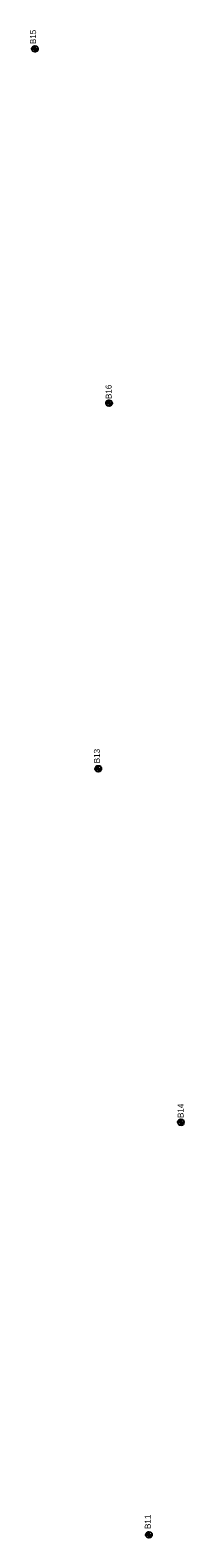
# Model space of a CAD drawing. Extents: x 345549 to 379569, y 127949 to 230467.
# Drawn here: x 361165 to 361421, y 134289 to 136793 of the extents above; entities that cross this region are included whole.
import ezdxf

# ---------------------------------------------------------------- set-up
doc = ezdxf.new("R2010")
doc.units = 0
for name, color, linetype in [('E_SOIL_BORE1 [KAPUR_CADDS_LEVELS]', 7, 'Continuous'), ('E_SOIL_BORE2 [KAPUR_CADDS_LEVELS]', 7, 'Continuous'), ('P_MARK', 7, 'Continuous')]:
    doc.layers.add(name, color=color, linetype=linetype)

msp = doc.modelspace()

# ---------------------------------------------------------------- linework, layer by layer
at = {"layer": 'P_MARK'}
for p, q in [((361173.1, 136766.5), (361173.1, 136756.5)), ((361168.1, 136761.5), (361178.1, 136761.5)), ((361291.4, 136173.3), (361301.4, 136173.3)), ((361296.4, 136178.3), (361296.4, 136168.3)), ((361273.5, 135566.2), (361283.5, 135566.2)), ((361278.5, 135571.2), (361278.5, 135561.2)), ((361410.9, 134979.1), (361420.9, 134979.1)), ((361415.9, 134984.1), (361415.9, 134974.1)), ((361357.8, 134294.1), (361367.8, 134294.1)), ((361362.8, 134299.1), (361362.8, 134289.1))]:
    msp.add_line(p, q, dxfattribs=at)
for centre in [(361173.1, 136761.5), (361296.4, 136173.3), (361278.5, 135566.2), (361415.9, 134979.1), (361362.8, 134294.1)]:
    msp.add_circle(centre, 5, dxfattribs=at)
for centre, radius, start, end in [((361173.1, 136761.5), 4.5, 89.9869, 179.9869), ((361173.1, 136761.5), 4, 89.9869, 179.9869), ((361173.1, 136761.5), 3.5, 89.9869, 179.9869), ((361173.1, 136761.5), 3, 89.9869, 179.9869), ((361173.1, 136761.5), 2.5, 89.9869, 179.9869), ((361173.1, 136761.5), 2, 89.9869, 179.9869), ((361173.1, 136761.5), 1.5, 89.9869, 179.9869), ((361173.1, 136761.5), 1, 89.9869, 179.9869), ((361173.1, 136761.5), 0.5, 89.9869, 179.9869), ((361173.1, 136761.5), 4.5, 269.9869, 359.9869), ((361173.1, 136761.5), 4, 269.9869, 359.9869), ((361173.1, 136761.5), 3.5, 269.9869, 359.9869), ((361173.1, 136761.5), 3, 269.9869, 359.9869), ((361173.1, 136761.5), 2.5, 269.9869, 359.9869), ((361173.1, 136761.5), 2, 269.9869, 359.9869), ((361173.1, 136761.5), 1.5, 269.9869, 359.9869), ((361173.1, 136761.5), 1, 269.9869, 359.9869), ((361173.1, 136761.5), 0.5, 269.9869, 359.9869), ((361296.4, 136173.3), 4.5, 89.9869, 179.9869), ((361296.4, 136173.3), 4, 89.9869, 179.9869), ((361296.4, 136173.3), 3.5, 89.9869, 179.9869), ((361296.4, 136173.3), 3, 89.9869, 179.9869), ((361296.4, 136173.3), 2.5, 89.9869, 179.9869), ((361296.4, 136173.3), 2, 89.9869, 179.9869), ((361296.4, 136173.3), 1.5, 89.9869, 179.9869), ((361296.4, 136173.3), 1, 89.9869, 179.9869), ((361296.4, 136173.3), 0.5, 89.9869, 179.9869), ((361296.4, 136173.3), 4.5, 269.9869, 359.9869), ((361296.4, 136173.3), 4, 269.9869, 359.9869), ((361296.4, 136173.3), 3.5, 269.9869, 359.9869), ((361296.4, 136173.3), 3, 269.9869, 359.9869), ((361296.4, 136173.3), 2.5, 269.9869, 359.9869), ((361296.4, 136173.3), 2, 269.9869, 359.9869), ((361296.4, 136173.3), 1.5, 269.9869, 359.9869), ((361296.4, 136173.3), 1, 269.9869, 359.9869), ((361296.4, 136173.3), 0.5, 269.9869, 359.9869), ((361278.5, 135566.2), 4.5, 89.9869, 179.9869), ((361278.5, 135566.2), 4, 89.9869, 179.9869), ((361278.5, 135566.2), 3.5, 89.9869, 179.9869), ((361278.5, 135566.2), 3, 89.9869, 179.9869), ((361278.5, 135566.2), 2.5, 89.9869, 179.9869), ((361278.5, 135566.2), 2, 89.9869, 179.9869), ((361278.5, 135566.2), 1.5, 89.9869, 179.9869), ((361278.5, 135566.2), 1, 89.9869, 179.9869), ((361278.5, 135566.2), 0.5, 89.9869, 179.9869), ((361278.5, 135566.2), 4.5, 269.9869, 359.9869), ((361278.5, 135566.2), 4, 269.9869, 359.9869), ((361278.5, 135566.2), 3.5, 269.9869, 359.9869), ((361278.5, 135566.2), 3, 269.9869, 359.9869), ((361278.5, 135566.2), 2.5, 269.9869, 359.9869), ((361278.5, 135566.2), 2, 269.9869, 359.9869), ((361278.5, 135566.2), 1.5, 269.9869, 359.9869), ((361278.5, 135566.2), 1, 269.9869, 359.9869), ((361278.5, 135566.2), 0.5, 269.9869, 359.9869), ((361415.9, 134979.1), 4.5, 89.9869, 179.9869), ((361415.9, 134979.1), 4, 89.9869, 179.9869), ((361415.9, 134979.1), 3.5, 89.9869, 179.9869), ((361415.9, 134979.1), 3, 89.9869, 179.9869), ((361415.9, 134979.1), 2.5, 89.9869, 179.9869), ((361415.9, 134979.1), 2, 89.9869, 179.9869), ((361415.9, 134979.1), 1.5, 89.9869, 179.9869), ((361415.9, 134979.1), 1, 89.9869, 179.9869), ((361415.9, 134979.1), 0.5, 89.9869, 179.9869), ((361415.9, 134979.1), 4.5, 269.9869, 359.9869), ((361415.9, 134979.1), 4, 269.9869, 359.9869), ((361415.9, 134979.1), 3.5, 269.9869, 359.9869), ((361415.9, 134979.1), 3, 269.9869, 359.9869), ((361415.9, 134979.1), 2.5, 269.9869, 359.9869), ((361415.9, 134979.1), 2, 269.9869, 359.9869), ((361415.9, 134979.1), 1.5, 269.9869, 359.9869), ((361415.9, 134979.1), 1, 269.9869, 359.9869), ((361415.9, 134979.1), 0.5, 269.9869, 359.9869), ((361362.8, 134294.1), 4.5, 89.9869, 179.9869), ((361362.8, 134294.1), 4, 89.9869, 179.9869), ((361362.8, 134294.1), 3.5, 89.9869, 179.9869), ((361362.8, 134294.1), 3, 89.9869, 179.9869), ((361362.8, 134294.1), 2.5, 89.9869, 179.9869), ((361362.8, 134294.1), 2, 89.9869, 179.9869), ((361362.8, 134294.1), 1.5, 89.9869, 179.9869), ((361362.8, 134294.1), 1, 89.9869, 179.9869), ((361362.8, 134294.1), 0.5, 89.9869, 179.9869), ((361362.8, 134294.1), 4.5, 269.9869, 359.9869), ((361362.8, 134294.1), 4, 269.9869, 359.9869), ((361362.8, 134294.1), 3.5, 269.9869, 359.9869), ((361362.8, 134294.1), 3, 269.9869, 359.9869), ((361362.8, 134294.1), 2.5, 269.9869, 359.9869), ((361362.8, 134294.1), 2, 269.9869, 359.9869), ((361362.8, 134294.1), 1.5, 269.9869, 359.9869), ((361362.8, 134294.1), 1, 269.9869, 359.9869), ((361362.8, 134294.1), 0.5, 269.9869, 359.9869)]:
    msp.add_arc(centre, radius, start, end, dxfattribs=at)

# ---------------------------------------------------------------- texts
at = {"layer": 'E_SOIL_BORE1 [KAPUR_CADDS_LEVELS]'}
for s, p in [('B13', (361281.2, 135575.3)), ('B14', (361420.3, 134986.3))]:
    msp.add_text(s, height=10, rotation=89.9869, dxfattribs=at).set_placement(p)
at = {"layer": 'E_SOIL_BORE2 [KAPUR_CADDS_LEVELS]'}
for s, p in [('B15', (361175.1, 136769.4)), ('B16', (361300.6, 136180.1)), ('B11', (361365.8, 134303.8))]:
    msp.add_text(s, height=10, rotation=89.9869, dxfattribs=at).set_placement(p)

doc.saveas('drawing.dxf')
